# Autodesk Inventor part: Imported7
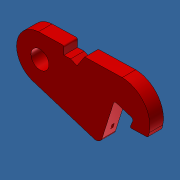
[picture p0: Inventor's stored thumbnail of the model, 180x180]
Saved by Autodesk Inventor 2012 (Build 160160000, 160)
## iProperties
Created: 2016-01
Part Number: Imported7
Material: Default
Document SubType Name: Modeling
Designer: Admin
Density: 1 g/cm^3
Author: Admin
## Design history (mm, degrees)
feature "Base1"
body "Solid1"
